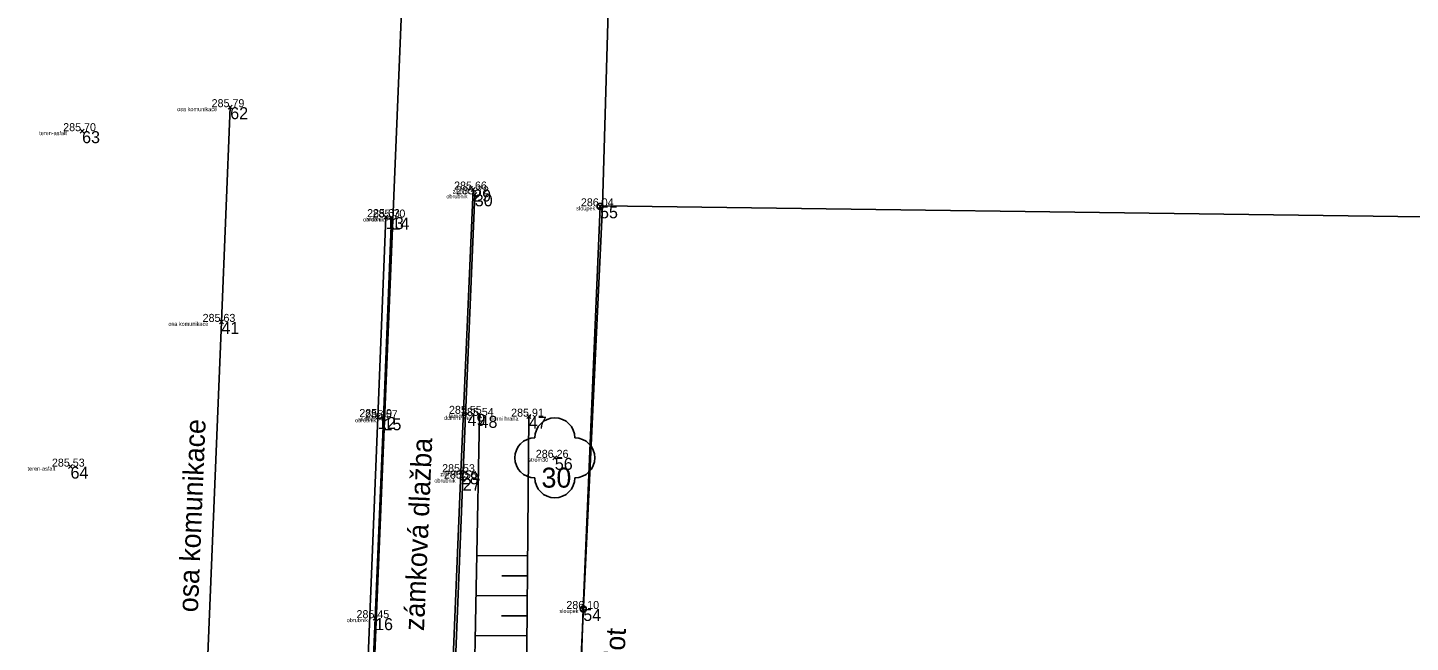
# Model space of a CAD drawing. Extents: x -456675 to -456278, y -1112395 to -1112217.
# Drawn here: x -456557.41 to -456522.87, y -1112300.26 to -1112284.88 of the extents above; entities that cross this region are included whole.
import ezdxf

# ---------------------------------------------------------------- set-up
doc = ezdxf.new("R2010")
doc.units = 0
for name, color, linetype in [('Cislo_bodu', 7, 'Continuous'), ('g_chodniky', 7, 'Continuous'), ('g_komunikace', 7, 'Continuous'), ('g_obrubnik', 7, 'Continuous'), ('g_ploty', 7, 'Continuous'), ('g_terenni_hrany', 7, 'Continuous'), ('g_vegetace', 7, 'Continuous'), ('Katastralni_mapa', 7, 'Continuous'), ('Kod_bodu', 7, 'Continuous'), ('Vyska_bodu', 7, 'Continuous'), ('Znacka_bodu', 7, 'Continuous')]:
    doc.layers.add(name, color=color, linetype=linetype)

msp = doc.modelspace()

# ---------------------------------------------------------------- linework, layer by layer
at = {"layer": 'g_chodniky'}
msp.add_lwpolyline([(-456546.28, -1112288.93), (-456546.59, -1112296), (-456546.83, -1112301.85)], dxfattribs=at)
at = {"layer": 'g_komunikace'}
for points in [[(-456552.35, -1112286.87), (-456552.57, -1112292.24), (-456553, -1112302.79), (-456553.35, -1112311.93), (-456553.71, -1112321.1)], [(-456549.54, -1112316.43), (-456549.21, -1112308.05), (-456549.01, -1112303.65), (-456548.9, -1112300.62), (-456548.66, -1112294.62), (-456548.46, -1112289.62)]]:
    msp.add_lwpolyline(points, dxfattribs=at)
at = {"layer": 'g_obrubnik'}
for points in [[(-456546.24, -1112289.05), (-456546.54, -1112296.16), (-456546.78, -1112302.15), (-456547.1, -1112310.15), (-456547.33, -1112316.6)], [(-456549.42, -1112316.59), (-456549.13, -1112309.61), (-456548.92, -1112304.61), (-456548.89, -1112303.64), (-456548.77, -1112300.63), (-456548.73, -1112299.65), (-456548.52, -1112294.65), (-456548.32, -1112289.63)]]:
    msp.add_lwpolyline(points, dxfattribs=at)
at = {"layer": 'g_ploty'}
msp.add_lwpolyline([(-456543.11, -1112289.35), (-456543.53, -1112299.42), (-456543.65, -1112302.81), (-456543.86, -1112306.04), (-456543.95, -1112309.4), (-456544.15, -1112312.82)], dxfattribs=at)
for centre in [(-456543.11, -1112289.35), (-456543.53, -1112299.42)]:
    msp.add_circle(centre, 0.075, dxfattribs=at)
at = {"layer": 'g_terenni_hrany'}
for p, q in [((-456546.187, -1112298.083), (-456544.919, -1112298.094)), ((-456545.56, -1112298.589), (-456544.923, -1112298.594)), ((-456546.207, -1112299.083), (-456544.927, -1112299.094)), ((-456545.574, -1112299.589), (-456544.931, -1112299.594)), ((-456546.226, -1112300.083), (-456544.936, -1112300.094))]:
    msp.add_line(p, q, dxfattribs=at)
for points in [[(-456546.63, -1112313.04), (-456546.27, -1112302.36), (-456546.12, -1112294.59)], [(-456544.89, -1112294.61), (-456544.97, -1112304.22), (-456545.27, -1112313.45)]]:
    msp.add_lwpolyline(points, dxfattribs=at)
at = {"layer": 'g_vegetace'}
msp.add_circle((-456544.24, -1112295.64), 0.0005, dxfattribs=at)
for centre, start, end in [((-456544.24, -1112295.14), 0, 180), ((-456544.74, -1112295.64), 90, 270), ((-456543.74, -1112295.64), 270, 90), ((-456544.24, -1112296.14), 180, 360)]:
    msp.add_arc(centre, 0.5, start, end, dxfattribs=at)
at = {"layer": 'Katastralni_mapa'}
for points in [[(-456541.36, -1112231.22), (-456543.05, -1112289.34)], [(-456546.55, -1112247.69), (-456550.87, -1112351.98)], [(-456545.12, -1112333.16), (-456543.05, -1112289.34)], [(-456543.05, -1112289.34), (-456487.163, -1112290.086)]]:
    msp.add_lwpolyline(points, dxfattribs=at)
at = {"layer": 'Znacka_bodu'}
for p, q in [((-456552.35, -1112286.87), (-456552.4, -1112286.82)), ((-456552.35, -1112286.87), (-456552.4, -1112286.92)), ((-456552.35, -1112286.87), (-456552.3, -1112286.82)), ((-456552.35, -1112286.87), (-456552.3, -1112286.92)), ((-456556.05, -1112287.47), (-456556.1, -1112287.42)), ((-456556.05, -1112287.47), (-456556.1, -1112287.52)), ((-456556.05, -1112287.47), (-456556, -1112287.42)), ((-456556.05, -1112287.47), (-456556, -1112287.52)), ((-456546.28, -1112288.93), (-456546.33, -1112288.88)), ((-456546.28, -1112288.93), (-456546.33, -1112288.98)), ((-456546.28, -1112288.93), (-456546.23, -1112288.88)), ((-456546.28, -1112288.93), (-456546.23, -1112288.98)), ((-456546.24, -1112289.05), (-456546.29, -1112289)), ((-456546.24, -1112289.05), (-456546.29, -1112289.1)), ((-456546.24, -1112289.05), (-456546.19, -1112289)), ((-456546.24, -1112289.05), (-456546.19, -1112289.1)), ((-456543.11, -1112289.35), (-456543.16, -1112289.3)), ((-456543.11, -1112289.35), (-456543.06, -1112289.3)), ((-456548.46, -1112289.62), (-456548.51, -1112289.57)), ((-456548.46, -1112289.62), (-456548.51, -1112289.67)), ((-456548.46, -1112289.62), (-456548.41, -1112289.57)), ((-456548.46, -1112289.62), (-456548.41, -1112289.67)), ((-456548.32, -1112289.63), (-456548.37, -1112289.58)), ((-456548.32, -1112289.63), (-456548.37, -1112289.68)), ((-456548.32, -1112289.63), (-456548.27, -1112289.58)), ((-456548.32, -1112289.63), (-456548.27, -1112289.68)), ((-456543.11, -1112289.35), (-456543.16, -1112289.4)), ((-456543.11, -1112289.35), (-456543.06, -1112289.4)), ((-456552.57, -1112292.24), (-456552.62, -1112292.19)), ((-456552.57, -1112292.24), (-456552.62, -1112292.29)), ((-456552.57, -1112292.24), (-456552.52, -1112292.19)), ((-456552.57, -1112292.24), (-456552.52, -1112292.29)), ((-456546.42, -1112294.54), (-456546.47, -1112294.49)), ((-456546.42, -1112294.54), (-456546.37, -1112294.49)), ((-456548.66, -1112294.62), (-456548.71, -1112294.57)), ((-456548.66, -1112294.62), (-456548.71, -1112294.67)), ((-456548.66, -1112294.62), (-456548.61, -1112294.57)), ((-456548.66, -1112294.62), (-456548.61, -1112294.67)), ((-456548.52, -1112294.65), (-456548.57, -1112294.6)), ((-456548.52, -1112294.65), (-456548.57, -1112294.7)), ((-456548.52, -1112294.65), (-456548.47, -1112294.6)), ((-456548.52, -1112294.65), (-456548.47, -1112294.7)), ((-456546.42, -1112294.54), (-456546.47, -1112294.59)), ((-456546.42, -1112294.54), (-456546.37, -1112294.59)), ((-456546.12, -1112294.59), (-456546.17, -1112294.54)), ((-456546.12, -1112294.59), (-456546.17, -1112294.64)), ((-456546.12, -1112294.59), (-456546.07, -1112294.54)), ((-456546.12, -1112294.59), (-456546.07, -1112294.64)), ((-456544.89, -1112294.61), (-456544.94, -1112294.56)), ((-456544.89, -1112294.61), (-456544.94, -1112294.66)), ((-456544.89, -1112294.61), (-456544.84, -1112294.56)), ((-456544.89, -1112294.61), (-456544.84, -1112294.66)), ((-456556.34, -1112295.86), (-456556.39, -1112295.81)), ((-456556.34, -1112295.86), (-456556.39, -1112295.91)), ((-456556.34, -1112295.86), (-456556.29, -1112295.81)), ((-456556.34, -1112295.86), (-456556.29, -1112295.91)), ((-456544.24, -1112295.64), (-456544.29, -1112295.59)), ((-456544.24, -1112295.64), (-456544.29, -1112295.69)), ((-456544.24, -1112295.64), (-456544.19, -1112295.59)), ((-456544.24, -1112295.64), (-456544.19, -1112295.69)), ((-456546.59, -1112296), (-456546.64, -1112295.95)), ((-456546.59, -1112296), (-456546.64, -1112296.05)), ((-456546.59, -1112296), (-456546.54, -1112295.95)), ((-456546.59, -1112296), (-456546.54, -1112296.05)), ((-456546.54, -1112296.16), (-456546.59, -1112296.11)), ((-456546.54, -1112296.16), (-456546.59, -1112296.21)), ((-456546.54, -1112296.16), (-456546.49, -1112296.11)), ((-456546.54, -1112296.16), (-456546.49, -1112296.21)), ((-456548.73, -1112299.65), (-456548.78, -1112299.6)), ((-456548.73, -1112299.65), (-456548.78, -1112299.7)), ((-456548.73, -1112299.65), (-456548.68, -1112299.6)), ((-456548.73, -1112299.65), (-456548.68, -1112299.7)), ((-456543.53, -1112299.42), (-456543.58, -1112299.37)), ((-456543.53, -1112299.42), (-456543.58, -1112299.47)), ((-456543.53, -1112299.42), (-456543.48, -1112299.37)), ((-456543.53, -1112299.42), (-456543.48, -1112299.47))]:
    msp.add_line(p, q, dxfattribs=at)

# ---------------------------------------------------------------- texts
at = {"layer": 'Cislo_bodu'}
for s, p in [('62', (-456552.35, -1112287.17)), ('63', (-456556.05, -1112287.77)), ('29', (-456546.28, -1112289.23)), ('30', (-456546.24, -1112289.35)), ('13', (-456548.46, -1112289.92)), ('14', (-456548.32, -1112289.93)), ('55', (-456543.11, -1112289.65)), ('41', (-456552.57, -1112292.54)), ('12', (-456548.66, -1112294.92)), ('15', (-456548.52, -1112294.95)), ('49', (-456546.42, -1112294.84)), ('48', (-456546.12, -1112294.89)), ('47', (-456544.89, -1112294.91)), ('64', (-456556.34, -1112296.16)), ('56', (-456544.24, -1112295.94)), ('28', (-456546.59, -1112296.3)), ('27', (-456546.54, -1112296.46)), ('16', (-456548.73, -1112299.95)), ('54', (-456543.53, -1112299.72))]:
    msp.add_text(s, height=0.3, dxfattribs=at).set_placement(p)
at = {"layer": 'g_chodniky'}
msp.add_text('zámková dlažba', height=0.5, rotation=87.5314, dxfattribs=at).set_placement((-456547.509, -1112299.978))
at = {"layer": 'g_komunikace'}
msp.add_text('osa komunikace', height=0.5, rotation=87.675, dxfattribs=at).set_placement((-456553.159, -1112299.508))
at = {"layer": 'g_ploty'}
msp.add_text('zničený drátěný plot', height=0.5, rotation=86.4834, dxfattribs=at).set_placement((-456542.825, -1112305.852))
at = {"layer": 'g_vegetace'}
msp.add_text('30', height=0.5, dxfattribs=at).set_placement((-456544.572, -1112296.386))
at = {"layer": 'Kod_bodu'}
for s, p in [('osa komunikace', (-456553.675, -1112286.97)), ('teren-asfalt', (-456557.123, -1112287.57)), ('zam.dl.', (-456546.792, -1112289.03)), ('obrubnik', (-456546.95, -1112289.15)), ('obrubnik', (-456549.03, -1112289.73)), ('silnice', (-456548.951, -1112289.72)), ('sloupek', (-456543.705, -1112289.45)), ('osa komunikace', (-456553.895, -1112292.34)), ('obrubnik', (-456549.23, -1112294.75)), ('silnice', (-456549.151, -1112294.72)), ('dolni hrana', (-456547.011, -1112294.69)), ('teren', (-456546.885, -1112294.64)), ('horni hrana', (-456545.846, -1112294.71)), ('teren-asfalt', (-456557.413, -1112295.96)), ('strom30', (-456544.903, -1112295.74)), ('obrubnik', (-456547.25, -1112296.26)), ('zam.dl.', (-456547.102, -1112296.1)), ('obrubnik', (-456549.44, -1112299.75)), ('sloupek', (-456544.125, -1112299.52))]:
    msp.add_text(s, height=0.1, dxfattribs=at).set_placement(p)
at = {"layer": 'Vyska_bodu'}
for s, p in [('285.79', (-456552.815, -1112286.87)), ('285.70', (-456556.523, -1112287.47)), ('285.66', (-456546.756, -1112288.93)), ('285.72', (-456546.705, -1112289.05)), ('286.04', (-456543.589, -1112289.35)), ('285.63', (-456548.93, -1112289.62)), ('285.70', (-456548.793, -1112289.63)), ('285.63', (-456553.04, -1112292.24)), ('285.49', (-456549.125, -1112294.62)), ('285.57', (-456548.985, -1112294.65)), ('285.55', (-456546.885, -1112294.54)), ('285.54', (-456546.585, -1112294.59)), ('285.91', (-456545.332, -1112294.61)), ('286.26', (-456544.716, -1112295.64)), ('285.53', (-456556.805, -1112295.86)), ('285.53', (-456547.055, -1112296)), ('285.56', (-456547.01, -1112296.16)), ('286.10', (-456543.952, -1112299.42)), ('285.45', (-456549.195, -1112299.65))]:
    msp.add_text(s, height=0.2, dxfattribs=at).set_placement(p)

doc.saveas('drawing.dxf')
